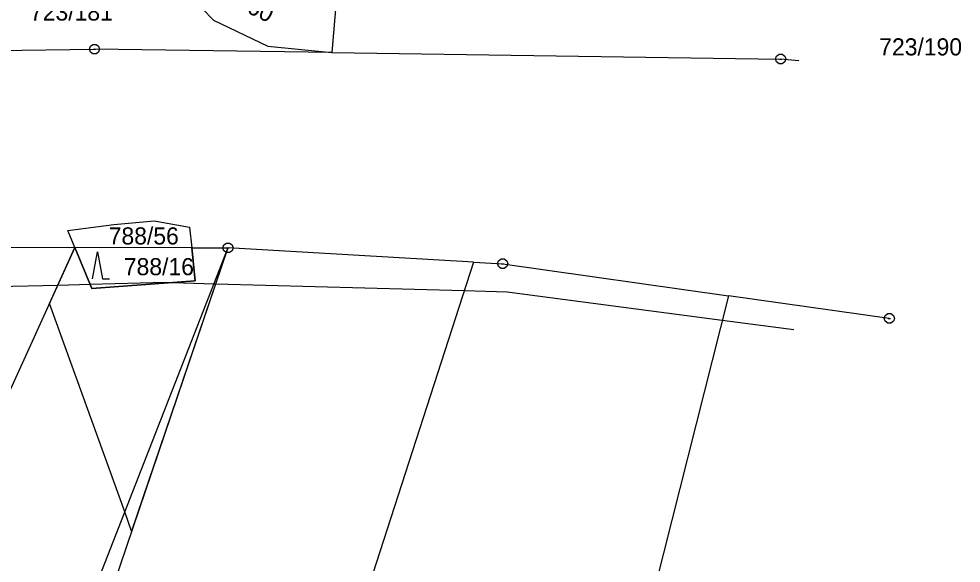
# Model space of a CAD drawing. Extents: x -759060 to -757386, y -1172273 to -1170948.
# Drawn here: x -757479 to -757385.5, y -1171174 to -1171120 of the extents above; entities that cross this region are included whole.
import ezdxf

# ---------------------------------------------------------------- set-up
doc = ezdxf.new("R2010")
doc.units = 0
for name, color, linetype in [('Vrstva 1', 7, 'Continuous'), ('Vrstva 11', 7, 'Continuous'), ('Vrstva 13', 7, 'Continuous'), ('Vrstva 2', 7, 'Continuous'), ('Vrstva 3', 7, 'Continuous'), ('Vrstva 8', 7, 'Continuous')]:
    doc.layers.add(name, color=color, linetype=linetype)

msp = doc.modelspace()

# ---------------------------------------------------------------- linework, layer by layer
at = {"layer": 'Vrstva 1'}
for p, q in [((-757463.38, -1171116.37), (-757459.72, -1171120.16)), ((-757447.51, -1171117.64), (-757447.97, -1171123.37)), ((-757459.72, -1171120.16), (-757454.32, -1171122.72)), ((-757487.21, -1171123.27), (-757471.52, -1171123.03)), ((-757447.97, -1171123.37), (-757471.52, -1171123.03)), ((-757454.32, -1171122.72), (-757447.97, -1171123.37)), ((-757447.97, -1171123.37), (-757403.45, -1171124.01)), ((-757401.65, -1171124.2), (-757403.45, -1171124.01)), ((-757401.65, -1171124.2), (-757401.65, -1171124.2)), ((-757469.61, -1171140.42), (-757465.61, -1171140.06)), ((-757465.61, -1171140.06), (-757462.09, -1171140.69)), ((-757474.18, -1171141.02), (-757469.61, -1171140.42)), ((-757473.48, -1171142.7), (-757474.18, -1171141.02)), ((-757462.09, -1171140.69), (-757461.88, -1171142.74)), ((-757494.59, -1171142.63), (-757473.48, -1171142.7)), ((-757473.48, -1171142.7), (-757494.18, -1171188.26)), ((-757458.28, -1171142.75), (-757484.05, -1171208.58)), ((-757458.28, -1171142.75), (-757483.99, -1171218.27)), ((-757471.79, -1171146.77), (-757473.48, -1171142.7)), ((-757461.88, -1171142.74), (-757473.48, -1171142.7)), ((-757461.88, -1171142.74), (-757461.53, -1171146.03)), ((-757461.88, -1171142.74), (-757458.28, -1171142.75)), ((-757433.93, -1171144.15), (-757458.28, -1171142.75)), ((-757433.93, -1171144.15), (-757466, -1171243.38)), ((-757433.93, -1171144.15), (-757431.02, -1171144.32)), ((-757431.02, -1171144.32), (-757408.63, -1171147.49)), ((-757461.53, -1171146.03), (-757471.79, -1171146.77)), ((-757408.63, -1171147.49), (-757425.57, -1171214.58)), ((-757392.67, -1171149.75), (-757408.63, -1171147.49)), ((-757392.67, -1171149.75), (-757392.67, -1171149.75))]:
    msp.add_line(p, q, dxfattribs=at)
at = {"layer": 'Vrstva 11'}
for p, q in [((-757497.55, -1171146.98), (-757475.17, -1171146.43)), ((-757475.17, -1171146.43), (-757471.97, -1171146.35)), ((-757471.97, -1171146.35), (-757464.51, -1171146.16)), ((-757464.51, -1171146.16), (-757463.69, -1171146.19)), ((-757463.69, -1171146.19), (-757459.67, -1171146.3)), ((-757459.67, -1171146.3), (-757459.49, -1171146.3)), ((-757459.49, -1171146.3), (-757434.84, -1171146.98)), ((-757434.84, -1171146.98), (-757430.58, -1171147.1)), ((-757430.58, -1171147.1), (-757409.24, -1171149.91)), ((-757409.24, -1171149.91), (-757402.15, -1171150.84))]:
    msp.add_line(p, q, dxfattribs=at)
at = {"layer": 'Vrstva 13'}
for p, q in [((-757476, -1171148.25), (-757473.48, -1171142.7)), ((-757473.48, -1171142.7), (-757471.79, -1171146.77)), ((-757458.28, -1171142.75), (-757467.85, -1171170.85)), ((-757461.53, -1171146.03), (-757461.88, -1171142.74)), ((-757461.88, -1171142.74), (-757458.28, -1171142.75)), ((-757471.79, -1171146.77), (-757461.53, -1171146.03)), ((-757468.53, -1171168.95), (-757476, -1171148.25)), ((-757467.85, -1171170.85), (-757468.53, -1171168.95))]:
    msp.add_line(p, q, dxfattribs=at)
at = {"layer": 'Vrstva 3'}
msp.add_lwpolyline([(-757471.722, -1171145.81), (-757471.22, -1171143.13), (-757470.718, -1171145.81), (-757470.048, -1171145.81)], dxfattribs=at)
at = {"layer": 'Vrstva 8'}
for p, q in [((-757471.64, -1171123.03), (-757471.4, -1171123.03)), ((-757403.57, -1171124.01), (-757403.33, -1171124.01)), ((-757458.4, -1171142.75), (-757458.16, -1171142.75)), ((-757431.14, -1171144.32), (-757430.9, -1171144.32)), ((-757392.79, -1171149.75), (-757392.55, -1171149.75))]:
    msp.add_line(p, q, dxfattribs=at)
for points in [[(-757471.37, -1171122.55), (-757471.12, -1171122.73), (-757471.02, -1171123.02), (-757471.12, -1171123.31), (-757471.37, -1171123.49), (-757471.68, -1171123.49), (-757471.93, -1171123.31), (-757472.03, -1171123.02), (-757471.93, -1171122.73), (-757471.68, -1171122.55)], [(-757403.3, -1171123.53), (-757403.05, -1171123.71), (-757402.95, -1171124), (-757403.05, -1171124.29), (-757403.3, -1171124.47), (-757403.61, -1171124.47), (-757403.86, -1171124.29), (-757403.96, -1171124), (-757403.86, -1171123.71), (-757403.61, -1171123.53)], [(-757458.13, -1171142.27), (-757457.88, -1171142.45), (-757457.78, -1171142.74), (-757457.88, -1171143.03), (-757458.13, -1171143.21), (-757458.44, -1171143.21), (-757458.69, -1171143.03), (-757458.79, -1171142.74), (-757458.69, -1171142.45), (-757458.44, -1171142.27)], [(-757430.87, -1171143.84), (-757430.62, -1171144.02), (-757430.52, -1171144.31), (-757430.62, -1171144.6), (-757430.87, -1171144.78), (-757431.18, -1171144.78), (-757431.43, -1171144.6), (-757431.53, -1171144.31), (-757431.43, -1171144.02), (-757431.18, -1171143.84)], [(-757392.52, -1171149.27), (-757392.27, -1171149.45), (-757392.17, -1171149.74), (-757392.27, -1171150.03), (-757392.52, -1171150.21), (-757392.83, -1171150.21), (-757393.08, -1171150.03), (-757393.18, -1171149.74), (-757393.08, -1171149.45), (-757392.83, -1171149.27)]]:
    msp.add_lwpolyline(points, close=True, dxfattribs=at)

# ---------------------------------------------------------------- texts
at = {"layer": 'Vrstva 2'}
msp.add_text('723/560', height=1.7, rotation=334.32087, dxfattribs=at).set_placement((-757461.661, -1171116.881))
for s, p in [('723/181', (-757477.923, -1171120.19)), ('723/190', (-757393.671, -1171123.65)), ('788/56', (-757470.113, -1171142.41)), ('788/16', (-757468.613, -1171145.46))]:
    msp.add_text(s, height=1.7, dxfattribs=at).set_placement(p)

doc.saveas('drawing.dxf')
